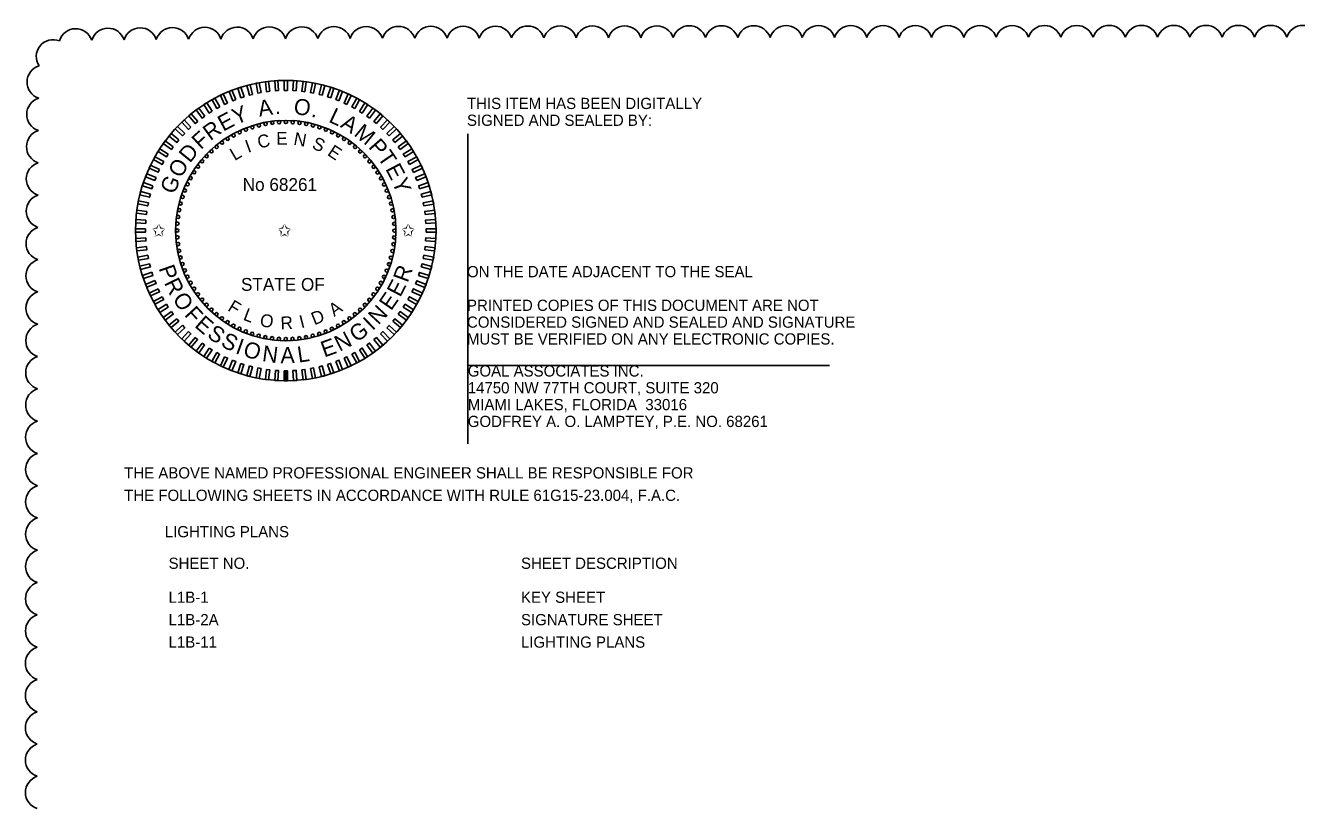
# Model space of a CAD drawing. Extents: x -811.2 to -795, y -2307.6 to -2235.1.
# Drawn here: x -811.11 to -803.18, y -2252.32 to -2247.44 of the extents above; entities that cross this region are included whole.
import ezdxf

# ---------------------------------------------------------------- set-up
doc = ezdxf.new("R2010")
doc.units = 0
for name, color, linetype in [('AdhocPoint_dp', 7, 'Continuous'), ('Cloud_dp', 7, 'Continuous'), ('Logo_dp', 7, 'Continuous'), ('TeleMisc', 7, 'Continuous'), ('TextDetails', 7, 'Continuous'), ('TextMisc', 7, 'Continuous')]:
    doc.layers.add(name, color=color, linetype=linetype)

msp = doc.modelspace()

# ---------------------------------------------------------------- linework, layer by layer
at = {"layer": 'AdhocPoint_dp'}
for p, q in [((-808.3546, -2248.1122), (-808.3546, -2250.0469)), ((-808.3546, -2249.5569), (-806.0979, -2249.5569))]:
    msp.add_line(p, q, dxfattribs=at)
at = {"layer": 'Cloud_dp'}
for centre, start, end in [((-810.8012, -2247.5613), 18.59454, 163.59454), ((-810.5999, -2247.5581), 18.21421, 163.21421), ((-810.3985, -2247.5559), 18.04696, 163.04696), ((-810.197, -2247.5542), 17.94666, 162.94666), ((-809.9955, -2247.5527), 17.87787, 162.87787), ((-809.794, -2247.5515), 17.82689, 162.82689), ((-809.5924, -2247.5504), 17.78716, 162.78716), ((-809.3909, -2247.5495), 17.75505, 162.75505), ((-809.1894, -2247.5486), 17.72841, 162.72841), ((-808.9878, -2247.5478), 17.70584, 162.70584), ((-808.7863, -2247.5471), 17.6864, 162.6864), ((-808.5848, -2247.5465), 17.66942, 162.66942), ((-808.3832, -2247.546), 17.65443, 162.65443), ((-808.1817, -2247.5454), 17.64106, 162.64106), ((-807.9801, -2247.545), 17.62905, 162.62905), ((-807.7786, -2247.5445), 17.61817, 162.61817), ((-807.577, -2247.5441), 17.60826, 162.60826), ((-807.3755, -2247.5438), 17.59919, 162.59919), ((-807.174, -2247.5434), 17.59084, 162.59084), ((-806.9724, -2247.5431), 17.58312, 162.58312), ((-806.7709, -2247.5428), 17.57595, 162.57595), ((-806.5693, -2247.5426), 17.56928, 162.56928), ((-806.3678, -2247.5424), 17.56305, 162.56305), ((-806.1662, -2247.5421), 17.55721, 162.55721), ((-805.9647, -2247.5419), 17.55172, 162.55172), ((-805.7631, -2247.5418), 17.54655, 162.54655), ((-805.5616, -2247.5416), 17.54167, 162.54167), ((-805.3601, -2247.5415), 17.53705, 162.53705), ((-805.1585, -2247.5414), 17.53267, 162.53267), ((-804.957, -2247.5413), 17.52851, 162.52851), ((-804.7554, -2247.5412), 17.52455, 162.52455), ((-804.5539, -2247.5411), 17.52079, 162.52079), ((-804.3523, -2247.541), 17.51719, 162.51719), ((-804.1508, -2247.541), 17.51375, 162.51375), ((-803.9492, -2247.5409), 17.51046, 162.51046), ((-803.7477, -2247.5409), 17.50731, 162.50731), ((-803.5461, -2247.5409), 17.50428, 162.50428), ((-803.3446, -2247.5409), 17.50138, 162.50138), ((-803.143, -2247.5409), 17.5, 162.5), ((-810.9414, -2247.6297), 68.43954, 213.43954), ((-810.999, -2247.7891), 106.80445, 251.80445), ((-811.001, -2247.9905), 107.04367, 252.04367), ((-811.0025, -2248.192), 107.15618, 252.15618), ((-811.0035, -2248.3935), 107.22533, 252.22533), ((-811.0044, -2248.595), 107.27338, 252.27338), ((-811.0052, -2248.7966), 107.30928, 252.30928), ((-811.0058, -2248.9981), 107.33743, 252.33743), ((-811.0063, -2249.1996), 107.36027, 252.36027), ((-811.0068, -2249.4012), 107.37928, 252.37928), ((-811.0072, -2249.6027), 107.39543, 252.39543), ((-811.0075, -2249.8042), 107.40937, 252.40937), ((-811.0078, -2250.0058), 107.42156, 252.42156), ((-811.0081, -2250.2073), 107.43234, 252.43234), ((-811.0083, -2250.4089), 107.44197, 252.44197), ((-811.0085, -2250.6104), 107.45063, 252.45063), ((-811.0086, -2250.812), 107.45847, 252.45847), ((-811.0088, -2251.0135), 107.46563, 252.46563), ((-811.0089, -2251.2151), 107.47218, 252.47218), ((-811.009, -2251.4166), 107.47822, 252.47822), ((-811.009, -2251.6181), 107.4838, 252.4838), ((-811.0091, -2251.8197), 107.48899, 252.48899), ((-811.0091, -2252.0212), 107.49382, 252.49382), ((-811.0091, -2252.2228), 107.49843, 252.49843)]:
    msp.add_arc(centre, 0.1057, start, end, dxfattribs=at)
at = {"layer": 'TextDetails'}
for radius in [0.9375, 0.6875]:
    msp.add_circle((-809.4901, -2248.7156), radius, dxfattribs=at)
at = {"layer": 'TextMisc'}
for p, q in [((-809.5001, -2249.6532), (-809.5003, -2249.5907)), ((-809.4901, -2249.6531), (-809.4903, -2249.5906)), ((-809.4801, -2249.6531), (-809.4803, -2249.5906))]:
    msp.add_line(p, q, dxfattribs=at)
for points in [[(-809.5897, -2247.8462), (-809.6097, -2247.8488), (-809.6175, -2247.7868), (-809.5975, -2247.7843)], [(-809.5349, -2247.8417), (-809.555, -2247.843), (-809.559, -2247.7806), (-809.5388, -2247.7794)], [(-809.4799, -2247.8406), (-809.5001, -2247.8406), (-809.5001, -2247.7782), (-809.4799, -2247.7782)], [(-809.425, -2247.843), (-809.4452, -2247.8417), (-809.4412, -2247.7794), (-809.4211, -2247.7807)], [(-809.3703, -2247.8488), (-809.3904, -2247.8463), (-809.3825, -2247.7843), (-809.3625, -2247.7868)], [(-809.8535, -2247.9195), (-809.8717, -2247.9281), (-809.8983, -2247.8716), (-809.8801, -2247.863)], [(-809.8028, -2247.8983), (-809.8215, -2247.9057), (-809.8445, -2247.8477), (-809.8258, -2247.8402)], [(-809.7508, -2247.8803), (-809.77, -2247.8865), (-809.7893, -2247.8271), (-809.7701, -2247.8209)], [(-809.6979, -2247.8656), (-809.7174, -2247.8706), (-809.7329, -2247.8101), (-809.7134, -2247.8051)], [(-809.6441, -2247.8542), (-809.6639, -2247.858), (-809.6756, -2247.7966), (-809.6558, -2247.7929)], [(-809.3162, -2247.858), (-809.336, -2247.8542), (-809.3243, -2247.7929), (-809.3045, -2247.7967)], [(-809.2626, -2247.8706), (-809.2822, -2247.8656), (-809.2667, -2247.8051), (-809.2471, -2247.8102)], [(-809.21, -2247.8866), (-809.2292, -2247.8803), (-809.2099, -2247.821), (-809.1907, -2247.8272)], [(-809.1585, -2247.9058), (-809.1773, -2247.8984), (-809.1543, -2247.8403), (-809.1355, -2247.8477)], [(-809.1083, -2247.9282), (-809.1266, -2247.9196), (-809.1, -2247.8631), (-809.0817, -2247.8717)], [(-809.9504, -2247.9714), (-809.9674, -2247.9822), (-810.0009, -2247.9295), (-809.9838, -2247.9186)], [(-809.9027, -2247.9439), (-809.9204, -2247.9537), (-809.9505, -2247.8989), (-809.9328, -2247.8892)], [(-809.0596, -2247.9537), (-809.0773, -2247.944), (-809.0473, -2247.8893), (-809.0296, -2247.899)], [(-809.0127, -2247.9823), (-809.0297, -2247.9715), (-808.9962, -2247.9187), (-808.9792, -2247.9296)], [(-810.0817, -2248.0708), (-810.0964, -2248.0846), (-810.1392, -2248.0391), (-810.1244, -2248.0253)], [(-810.04, -2248.0349), (-810.0556, -2248.0478), (-810.0954, -2247.9997), (-810.0798, -2247.9868)], [(-809.9962, -2248.0017), (-810.0125, -2248.0136), (-810.0492, -2247.9631), (-810.0329, -2247.9512)], [(-808.9676, -2248.0137), (-808.9839, -2248.0018), (-808.9472, -2247.9513), (-808.9308, -2247.9632)], [(-808.9245, -2248.0479), (-808.9401, -2248.035), (-808.9003, -2247.9869), (-808.8847, -2247.9998)], [(-808.8837, -2248.0847), (-808.8984, -2248.0709), (-808.8557, -2248.0254), (-808.841, -2248.0392)], [(-810.121, -2248.1092), (-810.1348, -2248.1239), (-810.1804, -2248.0812), (-810.1665, -2248.0665)], [(-808.8453, -2248.1241), (-808.8591, -2248.1093), (-808.8136, -2248.0666), (-808.7998, -2248.0813)], [(-810.192, -2248.1931), (-810.2039, -2248.2094), (-810.2544, -2248.1727), (-810.2426, -2248.1564)], [(-810.1579, -2248.15), (-810.1707, -2248.1656), (-810.2188, -2248.1258), (-810.206, -2248.1102)], [(-808.8094, -2248.1657), (-808.8223, -2248.1502), (-808.7742, -2248.1104), (-808.7613, -2248.1259)], [(-808.7762, -2248.2095), (-808.7881, -2248.1932), (-808.7376, -2248.1565), (-808.7257, -2248.1728)], [(-810.252, -2248.2852), (-810.2617, -2248.3028), (-810.3164, -2248.2728), (-810.3067, -2248.2551)], [(-810.2235, -2248.2382), (-810.2343, -2248.2552), (-810.287, -2248.2218), (-810.2762, -2248.2047)], [(-808.7459, -2248.2554), (-808.7567, -2248.2383), (-808.7039, -2248.2049), (-808.6931, -2248.2219)], [(-808.7184, -2248.303), (-808.7281, -2248.2853), (-808.6734, -2248.2552), (-808.6637, -2248.2729)], [(-810.2775, -2248.3338), (-810.2861, -2248.3521), (-810.3426, -2248.3255), (-810.334, -2248.3073)], [(-808.694, -2248.3523), (-808.7026, -2248.334), (-808.6461, -2248.3074), (-808.6375, -2248.3257)], [(-810.3192, -2248.4355), (-810.3254, -2248.4547), (-810.3848, -2248.4355), (-810.3786, -2248.4163)], [(-810.3, -2248.384), (-810.3074, -2248.4028), (-810.3654, -2248.3798), (-810.358, -2248.3611)], [(-808.6728, -2248.403), (-808.6802, -2248.3842), (-808.6222, -2248.3612), (-808.6147, -2248.38)], [(-808.6548, -2248.4549), (-808.661, -2248.4357), (-808.6016, -2248.4164), (-808.5954, -2248.4356)], [(-810.3351, -2248.4882), (-810.3401, -2248.5077), (-810.4006, -2248.4922), (-810.3956, -2248.4726)], [(-808.64, -2248.5079), (-808.6451, -2248.4883), (-808.5846, -2248.4728), (-808.5796, -2248.4924)], [(-810.3477, -2248.5417), (-810.3515, -2248.5615), (-810.4129, -2248.5498), (-810.4091, -2248.53)], [(-808.6287, -2248.5617), (-808.6325, -2248.5418), (-808.5711, -2248.5301), (-808.5673, -2248.55)], [(-810.3628, -2248.6505), (-810.3641, -2248.6707), (-810.4264, -2248.6668), (-810.4251, -2248.6466)], [(-810.357, -2248.5959), (-810.3595, -2248.6159), (-810.4215, -2248.6081), (-810.4189, -2248.588)], [(-808.6207, -2248.6161), (-808.6232, -2248.596), (-808.5613, -2248.5882), (-808.5588, -2248.6082)], [(-808.6162, -2248.6709), (-808.6174, -2248.6507), (-808.5551, -2248.6468), (-808.5539, -2248.6669)], [(-810.3652, -2248.7054), (-810.3652, -2248.7256), (-810.4276, -2248.7256), (-810.4276, -2248.7054)], [(-808.6151, -2248.7258), (-808.6151, -2248.7056), (-808.5527, -2248.7056), (-808.5527, -2248.7258)], [(-810.3641, -2248.7604), (-810.3628, -2248.7806), (-810.4251, -2248.7845), (-810.4264, -2248.7643)], [(-810.3595, -2248.8152), (-810.357, -2248.8352), (-810.4189, -2248.8431), (-810.4215, -2248.823)], [(-808.6233, -2248.8354), (-808.6207, -2248.8154), (-808.5588, -2248.8232), (-808.5613, -2248.8432)], [(-808.6175, -2248.7807), (-808.6162, -2248.7606), (-808.5539, -2248.7645), (-808.5551, -2248.7847)], [(-810.3516, -2248.8696), (-810.3478, -2248.8894), (-810.4091, -2248.9011), (-810.4129, -2248.8813)], [(-808.6325, -2248.8896), (-808.6287, -2248.8698), (-808.5674, -2248.8815), (-808.5712, -2248.9013)], [(-810.3402, -2248.9234), (-810.3352, -2248.9429), (-810.3957, -2248.9585), (-810.4007, -2248.9389)], [(-810.3255, -2248.9763), (-810.3192, -2248.9955), (-810.3786, -2249.0148), (-810.3849, -2248.9956)], [(-808.6611, -2248.9957), (-808.6548, -2248.9765), (-808.5954, -2248.9958), (-808.6017, -2249.015)], [(-808.6451, -2248.9431), (-808.6401, -2248.9236), (-808.5796, -2248.9391), (-808.5846, -2248.9586)], [(-810.3075, -2249.0283), (-810.3, -2249.0471), (-810.3581, -2249.07), (-810.3655, -2249.0513)], [(-808.6803, -2249.0472), (-808.6729, -2249.0285), (-808.6148, -2249.0514), (-808.6222, -2249.0702)], [(-810.2862, -2249.079), (-810.2776, -2249.0973), (-810.3341, -2249.1238), (-810.3427, -2249.1056)], [(-810.2618, -2249.1283), (-810.2521, -2249.1459), (-810.3068, -2249.176), (-810.3165, -2249.1583)], [(-808.7282, -2249.1461), (-808.7185, -2249.1284), (-808.6638, -2249.1585), (-808.6735, -2249.1762)], [(-808.7027, -2249.0974), (-808.6941, -2249.0792), (-808.6376, -2249.1057), (-808.6462, -2249.124)], [(-810.2344, -2249.1759), (-810.2236, -2249.1929), (-810.2763, -2249.2264), (-810.2871, -2249.2094)], [(-808.7568, -2249.1931), (-808.746, -2249.1761), (-808.6932, -2249.2095), (-808.704, -2249.2266)], [(-810.204, -2249.2217), (-810.1922, -2249.2381), (-810.2427, -2249.2748), (-810.2545, -2249.2584)], [(-810.1708, -2249.2656), (-810.158, -2249.2811), (-810.2061, -2249.3209), (-810.2189, -2249.3054)], [(-808.8224, -2249.2812), (-808.8095, -2249.2657), (-808.7614, -2249.3055), (-808.7743, -2249.321)], [(-808.7882, -2249.2382), (-808.7763, -2249.2219), (-808.7258, -2249.2586), (-808.7377, -2249.2749)], [(-810.135, -2249.3072), (-810.1211, -2249.3219), (-810.1667, -2249.3647), (-810.1805, -2249.35)], [(-810.0965, -2249.3465), (-810.0818, -2249.3603), (-810.1246, -2249.4059), (-810.1393, -2249.392)], [(-808.8985, -2249.3605), (-808.8838, -2249.3467), (-808.8411, -2249.3922), (-808.8558, -2249.406)], [(-808.8592, -2249.3221), (-808.8454, -2249.3073), (-808.7999, -2249.3501), (-808.8137, -2249.3648)], [(-810.0557, -2249.3834), (-810.0402, -2249.3962), (-810.08, -2249.4443), (-810.0955, -2249.4315)], [(-810.0127, -2249.4176), (-809.9964, -2249.4294), (-810.0331, -2249.4799), (-810.0494, -2249.4681)], [(-809.9676, -2249.449), (-809.9505, -2249.4598), (-809.984, -2249.5125), (-810.001, -2249.5017)], [(-809.0299, -2249.4599), (-809.0128, -2249.4491), (-808.9794, -2249.5018), (-808.9964, -2249.5126)], [(-808.984, -2249.4295), (-808.9677, -2249.4177), (-808.931, -2249.4682), (-808.9473, -2249.4801)], [(-808.9402, -2249.3964), (-808.9247, -2249.3835), (-808.8848, -2249.4316), (-808.9004, -2249.4445)], [(-809.9206, -2249.4775), (-809.9029, -2249.4872), (-809.933, -2249.542), (-809.9507, -2249.5322)], [(-809.8719, -2249.503), (-809.8536, -2249.5116), (-809.8802, -2249.5681), (-809.8985, -2249.5595)], [(-809.8217, -2249.5255), (-809.8029, -2249.5329), (-809.8259, -2249.591), (-809.8447, -2249.5835)], [(-809.1775, -2249.533), (-809.1587, -2249.5255), (-809.1357, -2249.5836), (-809.1545, -2249.591)], [(-809.1268, -2249.5117), (-809.1085, -2249.5031), (-809.0819, -2249.5596), (-809.1002, -2249.5682)], [(-809.0775, -2249.4873), (-809.0598, -2249.4776), (-809.0297, -2249.5323), (-809.0474, -2249.5421)], [(-809.7702, -2249.5447), (-809.751, -2249.5509), (-809.7703, -2249.6103), (-809.7895, -2249.6041)], [(-809.7176, -2249.5606), (-809.698, -2249.5657), (-809.7136, -2249.6261), (-809.7331, -2249.6211)], [(-809.6641, -2249.5733), (-809.6443, -2249.577), (-809.656, -2249.6384), (-809.6758, -2249.6346)], [(-809.6099, -2249.5825), (-809.5899, -2249.585), (-809.5977, -2249.647), (-809.6177, -2249.6444)], [(-809.5552, -2249.5883), (-809.5351, -2249.5896), (-809.539, -2249.6519), (-809.5592, -2249.6506)], [(-809.5003, -2249.5907), (-809.4801, -2249.5907), (-809.4801, -2249.6531), (-809.5003, -2249.6531)], [(-809.4453, -2249.5896), (-809.4252, -2249.5883), (-809.4213, -2249.6506), (-809.4414, -2249.6519)], [(-809.3906, -2249.585), (-809.3705, -2249.5825), (-809.3627, -2249.6445), (-809.3827, -2249.647)], [(-809.3362, -2249.5771), (-809.3163, -2249.5733), (-809.3046, -2249.6346), (-809.3245, -2249.6384)], [(-809.2824, -2249.5657), (-809.2628, -2249.5607), (-809.2473, -2249.6212), (-809.2668, -2249.6262)], [(-809.2294, -2249.551), (-809.2102, -2249.5447), (-809.1909, -2249.6041), (-809.2101, -2249.6104)]]:
    msp.add_lwpolyline(points, close=True, dxfattribs=at)
for centre in [(-809.7781, -2248.1024), (-809.739, -2248.0855), (-809.6989, -2248.0712), (-809.6581, -2248.0593), (-809.6165, -2248.0501), (-809.5745, -2248.0434), (-809.5321, -2248.0395), (-809.4896, -2248.0382), (-809.447, -2248.0395), (-809.4047, -2248.0436), (-809.3626, -2248.0503), (-809.3211, -2248.0596), (-809.2802, -2248.0715), (-809.2402, -2248.0859), (-809.2012, -2248.1029), (-809.9215, -2248.1933), (-809.8879, -2248.1672), (-809.8527, -2248.1433), (-809.816, -2248.1217), (-809.1633, -2248.1222), (-809.1266, -2248.1439), (-809.0915, -2248.1679), (-809.0579, -2248.194), (-809.9836, -2248.2515), (-809.9535, -2248.2214), (-809.026, -2248.2222), (-808.9959, -2248.2523), (-810.0618, -2248.3522), (-810.0379, -2248.317), (-810.0118, -2248.2834), (-808.9678, -2248.2842), (-808.9417, -2248.3179), (-808.9178, -2248.3531), (-810.1029, -2248.4267), (-810.0835, -2248.3888), (-808.8962, -2248.3898), (-808.8769, -2248.4277), (-810.1343, -2248.5057), (-810.1198, -2248.4657), (-808.86, -2248.4668), (-808.8456, -2248.5068), (-810.1555, -2248.5881), (-810.1462, -2248.5466), (-808.8338, -2248.5477), (-808.8245, -2248.5892), (-810.1622, -2248.6302), (-808.8179, -2248.6313), (-810.1676, -2248.7151), (-810.1662, -2248.6725), (-808.814, -2248.6737), (-808.8127, -2248.7162), (-810.1663, -2248.7576), (-810.1623, -2248.8), (-808.8181, -2248.8011), (-808.814, -2248.7587), (-810.1557, -2248.842), (-810.1464, -2248.8836), (-808.8341, -2248.8847), (-808.8248, -2248.8431), (-810.1346, -2248.9244), (-810.1202, -2248.9645), (-808.8604, -2248.9656), (-808.846, -2248.9255), (-810.1034, -2249.0036), (-810.0841, -2249.0415), (-808.8967, -2249.0425), (-808.8774, -2249.0046), (-810.0624, -2249.0782), (-810.0385, -2249.1134), (-808.9424, -2249.1143), (-808.9184, -2249.0791), (-810.0125, -2249.147), (-809.9844, -2249.179), (-809.9543, -2249.2091), (-809.0268, -2249.2099), (-808.9967, -2249.1798), (-808.9685, -2249.1479), (-809.9224, -2249.2373), (-809.8888, -2249.2634), (-809.8536, -2249.2873), (-809.1276, -2249.2879), (-809.0924, -2249.264), (-809.0587, -2249.238), (-809.817, -2249.309), (-809.7791, -2249.3284), (-809.74, -2249.3453), (-809.7, -2249.3598), (-809.6591, -2249.3717), (-809.6176, -2249.381), (-809.3637, -2249.3812), (-809.3222, -2249.372), (-809.2813, -2249.3601), (-809.2413, -2249.3457), (-809.2022, -2249.3289), (-809.1642, -2249.3096), (-809.5756, -2249.3877), (-809.5332, -2249.3917), (-809.4901, -2249.3931), (-809.4481, -2249.3918), (-809.4058, -2249.3878)]:
    msp.add_circle(centre, 0.01, dxfattribs=at)

# ---------------------------------------------------------------- texts
at = {"layer": 'Logo_dp'}
for s, p in [('THIS ITEM HAS BEEN DIGITALLY', (-808.3596, -2247.9571)), ('SIGNED AND SEALED BY:', (-808.3596, -2248.0621)), ('ON THE DATE ADJACENT TO THE SEAL', (-808.3596, -2249.0071)), ('PRINTED COPIES OF THIS DOCUMENT ARE NOT ', (-808.3596, -2249.2171)), ('CONSIDERED SIGNED AND SEALED AND SIGNATURE ', (-808.3596, -2249.3221)), ('MUST BE VERIFIED ON ANY ELECTRONIC COPIES.', (-808.3596, -2249.4271)), ('GOAL ASSOCIATES INC.', (-808.3546, -2249.6269)), ('14750 NW 77TH COURT, SUITE 320', (-808.3546, -2249.7319)), ('MIAMI LAKES, FLORIDA  33016', (-808.3546, -2249.8369)), ('GODFREY A. O. LAMPTEY, P.E. NO. 68261', (-808.3546, -2249.9419)), ('THE ABOVE NAMED PROFESSIONAL ENGINEER SHALL BE RESPONSIBLE FOR ', (-810.4987, -2250.2631)), ('THE FOLLOWING SHEETS IN ACCORDANCE WITH RULE 61G15-23.004, F.A.C.', (-810.4987, -2250.4031)), ('LIGHTING PLANS', (-810.245, -2250.6301))]:
    msp.add_text(s, height=0.07, dxfattribs=at).set_placement(p)
at = {"layer": 'TeleMisc'}
for s, p in [('SHEET NO.', (-810.2215, -2250.8271)), ('SHEET DESCRIPTION', (-808.0226, -2250.8271)), ('L1B-1', (-810.2215, -2251.0393)), ('KEY SHEET', (-808.0226, -2251.0393)), ('L1B-2A', (-810.2215, -2251.1793)), ('SIGNATURE SHEET', (-808.0226, -2251.1793)), ('L1B-11', (-810.2215, -2251.3193)), ('LIGHTING PLANS', (-808.0226, -2251.3193))]:
    msp.add_text(s, height=0.07, dxfattribs=at).set_placement(p)
at = {"layer": 'TextMisc'}
for s, height, rotation, p in [('Y', 0.1, 21.06329, (-809.8021, -2248.0562)), ('A', 0.1, 8.80884, (-809.6551, -2248.005)), ('O', 0.1, 352.18771, (-809.4449, -2247.9875)), ('E', 0.1, 28.10553, (-809.8806, -2248.0994)), ('.', 0.1, 1.04184, (-809.5575, -2247.9892)), ('.', 0.1, 343.52684, (-809.3358, -2248.0026)), ('L', 0.1, 334.67271, (-809.2279, -2248.0349)), ('A', 0.1, 328.40959, (-809.1552, -2248.0676)), ('F', 0.1, 42.37723, (-810.0205, -2248.2147)), ('R', 0.1, 35.92688, (-809.9609, -2248.1583)), ('E', 0.08, 0.41861, (-809.5498, -2248.1806)), ('N', 0.08, 349.29143, (-809.4455, -2248.1791)), ('M', 0.1, 320.6426, (-809.0707, -2248.1188)), ('D', 0.1, 50.8569, (-810.0886, -2248.2984)), ('I', 0.08, 20.01168, (-809.7258, -2248.2316)), ('C', 0.08, 12.20255, (-809.6579, -2248.204)), ('S', 0.08, 337.02207, (-809.3325, -2248.2008)), ('E', 0.08, 325.86633, (-809.2358, -2248.2411)), ('P', 0.1, 311.19658, (-808.9784, -2248.1957)), ('L', 0.08, 30.40215, (-809.8093, -2248.282)), ('T', 0.1, 304.45632, (-808.9209, -2248.2594)), ('O', 0.1, 59.51777, (-810.1446, -2248.3933)), ('E', 0.1, 297.63152, (-808.8707, -2248.3302)), ('G', 0.1, 68.0518, (-810.1851, -2248.494)), ('Y', 0.1, 290.58928, (-808.8281, -2248.4091)), ('P', 0.1, 289.40551, (-810.2848, -2248.9502)), ('R', 0.1, 69.5134, (-808.7299, -2249.0453)), ('R', 0.1, 296.14576, (-810.2518, -2249.0419)), ('E', 0.1, 62.47116, (-808.7761, -2249.136)), ('O', 0.1, 303.96711, (-810.2003, -2249.1425)), ('E', 0.1, 55.42892, (-808.833, -2249.2204)), ('F', 0.1, 312.62798, (-810.1279, -2249.2446)), ('F', 0.08, 328.72408, (-809.8582, -2249.2122)), ('L', 0.08, 339.29159, (-809.7609, -2249.2713)), ('D', 0.08, 22.01279, (-809.312, -2249.3075)), ('A', 0.08, 34.49917, (-809.1883, -2249.255)), ('N', 0.1, 47.17876, (-808.9123, -2249.3095)), ('E', 0.1, 319.07833, (-810.0645, -2249.3129)), ('O', 0.08, 349.68206, (-809.6562, -2249.311)), ('R', 0.08, 2.33977, (-809.5217, -2249.3329)), ('I', 0.08, 14.20366, (-809.3941, -2249.3262)), ('G', 0.1, 35.11153, (-809.0492, -2249.4172)), ('I', 0.1, 43.64556, (-808.9499, -2249.344)), ('S', 0.1, 326.12056, (-809.9869, -2249.3788)), ('S', 0.1, 333.193, (-809.9015, -2249.4349)), ('N', 0.1, 26.86136, (-809.1544, -2249.4732)), ('I', 0.1, 340.26543, (-809.8098, -2249.4801)), ('O', 0.1, 343.79863, (-809.7621, -2249.4983)), ('N', 0.1, 352.45949, (-809.6411, -2249.5304)), ('A', 0.1, 0.70966, (-809.5227, -2249.5436)), ('L', 0.1, 8.47665, (-809.4105, -2249.5404)), ('E', 0.1, 19.81912, (-809.2498, -2249.5086))]:
    msp.add_text(s, height=height, rotation=rotation, dxfattribs=at).set_placement(p)
for s, p in [('No 68261', (-809.7591, -2248.4684)), ('✩', (-810.3251, -2248.7536)), ('✩', (-809.5404, -2248.7536)), ('✩', (-808.7685, -2248.7536)), ('STATE OF', (-809.7698, -2249.0918))]:
    msp.add_text(s, height=0.08, dxfattribs=at).set_placement(p)

doc.saveas('drawing.dxf')
